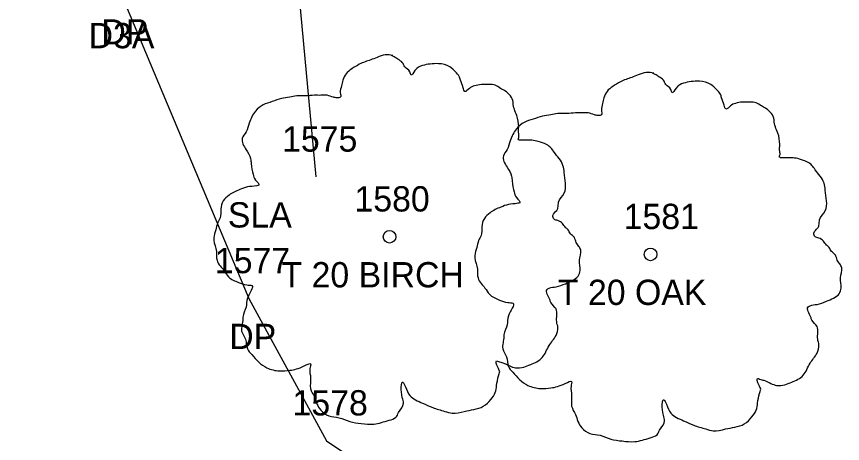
# Model space of a CAD drawing. Extents: x 1964982 to 1970452, y 1116335 to 1119906.
# Drawn here: x 1966585.21 to 1966617.84, y 1117418.71 to 1117435.59 of the extents above; entities that cross this region are included whole.
import ezdxf

# ---------------------------------------------------------------- set-up
doc = ezdxf.new("R2010")
doc.units = 0
for name, color, linetype in [('RD_EX_Driveway', 7, 'Continuous'), ('RD_EX_Driveway_txCode', 7, 'Continuous'), ('RD_EX_VEG', 7, 'Continuous'), ('RD_EX_VEG_txCode', 7, 'Continuous'), ('RD_SMD_Locator', 7, 'Continuous')]:
    doc.layers.add(name, color=color, linetype=linetype)

msp = doc.modelspace()

# ---------------------------------------------------------------- linework, layer by layer
at = {"layer": 'RD_EX_Driveway'}
msp.add_lwpolyline([(1966578.388, 1117408.593), (1966578.939, 1117419.648), (1966578.028, 1117435.239), (1966589.341, 1117436.481), (1966594.391, 1117424.44), (1966597.459, 1117418.815), (1966604.527, 1117414.058)], dxfattribs=at)
at = {"layer": 'RD_EX_VEG'}
msp.add_line((1966597.045, 1117429.245), (1966593.432, 1117467.989), dxfattribs=at)
for centre, radius in [((1966599.944, 1117426.878), 0.25), ((1966599.944, 1117426.878), 0.25), ((1966599.931, 1117426.86), 0.0001), ((1966599.931, 1117426.86), 0.0001), ((1966610.256, 1117426.183), 0.25), ((1966610.256, 1117426.183), 0.25), ((1966610.244, 1117426.164), 0.0001), ((1966610.244, 1117426.164), 0.0001)]:
    msp.add_circle(centre, radius, dxfattribs=at)
for points in [[(1966600.075, 1117434.046), (1966599.776, 1117434.071), (1966599.451, 1117433.971), (1966599.201, 1117433.871), (1966598.976, 1117433.796), (1966598.751, 1117433.696), (1966598.451, 1117433.521), (1966598.226, 1117433.321), (1966598.101, 1117433.071), (1966598.051, 1117432.846), (1966598.001, 1117432.571), (1966598.001, 1117432.396), (1966597.876, 1117432.371), (1966597.726, 1117432.396), (1966597.477, 1117432.471), (1966597.227, 1117432.471), (1966596.977, 1117432.471), (1966596.627, 1117432.446), (1966596.277, 1117432.446), (1966596.002, 1117432.396), (1966595.677, 1117432.346), (1966595.303, 1117432.221), (1966594.953, 1117432.096), (1966594.653, 1117431.847), (1966594.403, 1117431.372), (1966594.278, 1117431.022), (1966594.128, 1117430.772), (1966594.278, 1117430.322), (1966594.453, 1117429.972), (1966594.478, 1117429.772), (1966594.553, 1117429.348), (1966594.653, 1117429.123), (1966594.778, 1117428.923), (1966594.703, 1117428.898), (1966594.328, 1117428.848), (1966594.028, 1117428.748), (1966593.603, 1117428.523), (1966593.378, 1117428.298), (1966593.278, 1117427.973), (1966593.253, 1117427.623), (1966593.154, 1117427.424), (1966593.079, 1117427.149), (1966593.054, 1117427.074), (1966593.004, 1117426.749), (1966593.104, 1117426.299), (1966593.129, 1117425.949), (1966593.253, 1117425.724), (1966593.403, 1117425.549), (1966593.578, 1117425.299), (1966593.978, 1117425.075), (1966594.303, 1117424.975), (1966594.503, 1117424.95), (1966594.328, 1117424.45), (1966594.278, 1117424.1), (1966594.153, 1117423.7), (1966594.153, 1117423.625), (1966594.103, 1117423.15), (1966594.253, 1117422.825), (1966594.328, 1117422.451), (1966594.503, 1117422.226), (1966594.778, 1117421.926), (1966595.103, 1117421.701), (1966595.602, 1117421.576), (1966596.002, 1117421.601), (1966596.577, 1117421.776), (1966596.827, 1117421.851), (1966596.802, 1117421.676), (1966596.827, 1117421.301), (1966596.827, 1117420.876), (1966596.977, 1117420.552), (1966597.077, 1117420.277), (1966597.227, 1117420.027), (1966597.552, 1117419.802), (1966597.951, 1117419.727), (1966598.376, 1117419.577), (1966598.826, 1117419.502), (1966599.326, 1117419.477), (1966599.926, 1117419.627), (1966600.2, 1117419.752), (1966600.3, 1117419.927), (1966600.5, 1117420.302), (1966600.45, 1117420.527), (1966600.475, 1117421.126), (1966600.575, 1117420.951), (1966600.75, 1117420.601), (1966601.25, 1117420.302), (1966601.65, 1117420.127), (1966602.125, 1117419.977), (1966602.424, 1117419.902), (1966602.899, 1117419.977), (1966603.274, 1117420.052), (1966603.649, 1117420.177), (1966603.949, 1117420.452), (1966604.124, 1117420.726), (1966604.174, 1117421.001), (1966604.249, 1117421.376), (1966604.299, 1117421.551)], [(1966600.075, 1117434.046), (1966599.776, 1117434.071), (1966599.451, 1117433.971), (1966599.201, 1117433.871), (1966598.976, 1117433.796), (1966598.751, 1117433.696), (1966598.451, 1117433.521), (1966598.226, 1117433.321), (1966598.101, 1117433.071), (1966598.051, 1117432.846), (1966598.001, 1117432.571), (1966598.001, 1117432.396), (1966597.876, 1117432.371), (1966597.726, 1117432.396), (1966597.477, 1117432.471), (1966597.227, 1117432.471), (1966596.977, 1117432.471), (1966596.627, 1117432.446), (1966596.277, 1117432.446), (1966596.002, 1117432.396), (1966595.677, 1117432.346), (1966595.303, 1117432.221), (1966594.953, 1117432.096), (1966594.653, 1117431.847), (1966594.403, 1117431.372), (1966594.278, 1117431.022), (1966594.128, 1117430.772), (1966594.278, 1117430.322), (1966594.453, 1117429.972), (1966594.478, 1117429.772), (1966594.553, 1117429.348), (1966594.653, 1117429.123), (1966594.778, 1117428.923), (1966594.703, 1117428.898), (1966594.328, 1117428.848), (1966594.028, 1117428.748), (1966593.603, 1117428.523), (1966593.378, 1117428.298), (1966593.278, 1117427.973), (1966593.253, 1117427.623), (1966593.154, 1117427.424), (1966593.079, 1117427.149), (1966593.054, 1117427.074), (1966593.004, 1117426.749), (1966593.104, 1117426.299), (1966593.129, 1117425.949), (1966593.253, 1117425.724), (1966593.403, 1117425.549), (1966593.578, 1117425.299), (1966593.978, 1117425.075), (1966594.303, 1117424.975), (1966594.503, 1117424.95), (1966594.328, 1117424.45), (1966594.278, 1117424.1), (1966594.153, 1117423.7), (1966594.153, 1117423.625), (1966594.103, 1117423.15), (1966594.253, 1117422.825), (1966594.328, 1117422.451), (1966594.503, 1117422.226), (1966594.778, 1117421.926), (1966595.103, 1117421.701), (1966595.602, 1117421.576), (1966596.002, 1117421.601), (1966596.577, 1117421.776), (1966596.827, 1117421.851), (1966596.802, 1117421.676), (1966596.827, 1117421.301), (1966596.827, 1117420.876), (1966596.977, 1117420.552), (1966597.077, 1117420.277), (1966597.227, 1117420.027), (1966597.552, 1117419.802), (1966597.951, 1117419.727), (1966598.376, 1117419.577), (1966598.826, 1117419.502), (1966599.326, 1117419.477), (1966599.926, 1117419.627), (1966600.2, 1117419.752), (1966600.3, 1117419.927), (1966600.5, 1117420.302), (1966600.45, 1117420.527), (1966600.475, 1117421.126), (1966600.575, 1117420.951), (1966600.75, 1117420.601), (1966601.25, 1117420.302), (1966601.65, 1117420.127), (1966602.125, 1117419.977), (1966602.424, 1117419.902), (1966602.899, 1117419.977), (1966603.274, 1117420.052), (1966603.649, 1117420.177), (1966603.949, 1117420.452), (1966604.124, 1117420.726), (1966604.174, 1117421.001), (1966604.249, 1117421.376), (1966604.299, 1117421.551)], [(1966604.299, 1117421.551), (1966604.224, 1117421.726), (1966604.174, 1117421.976), (1966604.249, 1117421.951), (1966604.424, 1117421.901), (1966604.698, 1117421.776), (1966604.923, 1117421.701), (1966605.248, 1117421.726), (1966605.523, 1117421.826), (1966605.973, 1117422.101), (1966606.248, 1117422.576), (1966606.523, 1117422.975), (1966606.598, 1117423.3), (1966606.548, 1117423.525), (1966606.523, 1117424.025), (1966606.323, 1117424.275), (1966606.273, 1117424.4), (1966606.173, 1117424.8), (1966606.248, 1117424.85), (1966606.523, 1117424.9), (1966606.897, 1117425.025), (1966607.172, 1117425.149), (1966607.397, 1117425.324), (1966607.472, 1117425.549), (1966607.447, 1117425.949), (1966607.497, 1117426.349), (1966607.422, 1117426.499), (1966607.322, 1117426.649), (1966607.247, 1117426.849), (1966607.097, 1117426.999), (1966606.997, 1117427.149), (1966606.897, 1117427.249), (1966606.773, 1117427.399), (1966606.598, 1117427.523), (1966606.448, 1117427.573), (1966606.398, 1117427.723), (1966606.548, 1117427.923), (1966606.598, 1117428.023), (1966606.623, 1117428.248), (1966606.848, 1117428.598), (1966606.897, 1117428.998), (1966606.848, 1117429.423), (1966606.798, 1117429.698), (1966606.648, 1117429.972), (1966606.448, 1117430.222), (1966606.323, 1117430.397), (1966606.148, 1117430.522), (1966605.823, 1117430.647), (1966605.573, 1117430.697), (1966605.223, 1117430.697), (1966605.023, 1117430.747), (1966605.048, 1117430.797), (1966605.048, 1117430.947), (1966605.048, 1117431.222), (1966604.973, 1117431.672), (1966604.823, 1117432.171), (1966604.823, 1117432.196), (1966604.723, 1117432.446), (1966604.499, 1117432.646), (1966604.324, 1117432.746), (1966604.124, 1117432.871), (1966603.874, 1117432.896), (1966603.574, 1117432.896), (1966603.299, 1117432.846), (1966603.099, 1117432.746), (1966602.924, 1117432.621), (1966602.849, 1117432.771), (1966602.749, 1117433.071), (1966602.699, 1117433.221), (1966602.549, 1117433.396), (1966602.325, 1117433.596), (1966601.875, 1117433.721), (1966601.25, 1117433.646), (1966600.95, 1117433.446), (1966600.8, 1117433.271), (1966600.75, 1117433.396), (1966600.55, 1117433.596), (1966600.45, 1117433.771), (1966600.275, 1117433.896), (1966600.125, 1117433.996), (1966600.025, 1117434.046)], [(1966604.299, 1117421.551), (1966604.224, 1117421.726), (1966604.174, 1117421.976), (1966604.249, 1117421.951), (1966604.424, 1117421.901), (1966604.698, 1117421.776), (1966604.923, 1117421.701), (1966605.248, 1117421.726), (1966605.523, 1117421.826), (1966605.973, 1117422.101), (1966606.248, 1117422.576), (1966606.523, 1117422.975), (1966606.598, 1117423.3), (1966606.548, 1117423.525), (1966606.523, 1117424.025), (1966606.323, 1117424.275), (1966606.273, 1117424.4), (1966606.173, 1117424.8), (1966606.248, 1117424.85), (1966606.523, 1117424.9), (1966606.897, 1117425.025), (1966607.172, 1117425.149), (1966607.397, 1117425.324), (1966607.472, 1117425.549), (1966607.447, 1117425.949), (1966607.497, 1117426.349), (1966607.422, 1117426.499), (1966607.322, 1117426.649), (1966607.247, 1117426.849), (1966607.097, 1117426.999), (1966606.997, 1117427.149), (1966606.897, 1117427.249), (1966606.773, 1117427.399), (1966606.598, 1117427.523), (1966606.448, 1117427.573), (1966606.398, 1117427.723), (1966606.548, 1117427.923), (1966606.598, 1117428.023), (1966606.623, 1117428.248), (1966606.848, 1117428.598), (1966606.897, 1117428.998), (1966606.848, 1117429.423), (1966606.798, 1117429.698), (1966606.648, 1117429.972), (1966606.448, 1117430.222), (1966606.323, 1117430.397), (1966606.148, 1117430.522), (1966605.823, 1117430.647), (1966605.573, 1117430.697), (1966605.223, 1117430.697), (1966605.023, 1117430.747), (1966605.048, 1117430.797), (1966605.048, 1117430.947), (1966605.048, 1117431.222), (1966604.973, 1117431.672), (1966604.823, 1117432.171), (1966604.823, 1117432.196), (1966604.723, 1117432.446), (1966604.499, 1117432.646), (1966604.324, 1117432.746), (1966604.124, 1117432.871), (1966603.874, 1117432.896), (1966603.574, 1117432.896), (1966603.299, 1117432.846), (1966603.099, 1117432.746), (1966602.924, 1117432.621), (1966602.849, 1117432.771), (1966602.749, 1117433.071), (1966602.699, 1117433.221), (1966602.549, 1117433.396), (1966602.325, 1117433.596), (1966601.875, 1117433.721), (1966601.25, 1117433.646), (1966600.95, 1117433.446), (1966600.8, 1117433.271), (1966600.75, 1117433.396), (1966600.55, 1117433.596), (1966600.45, 1117433.771), (1966600.275, 1117433.896), (1966600.125, 1117433.996), (1966600.025, 1117434.046)], [(1966610.388, 1117433.35), (1966610.088, 1117433.375), (1966609.763, 1117433.275), (1966609.514, 1117433.175), (1966609.289, 1117433.1), (1966609.064, 1117433), (1966608.764, 1117432.825), (1966608.539, 1117432.625), (1966608.414, 1117432.375), (1966608.364, 1117432.151), (1966608.314, 1117431.876), (1966608.314, 1117431.701), (1966608.189, 1117431.676), (1966608.039, 1117431.701), (1966607.789, 1117431.776), (1966607.539, 1117431.776), (1966607.289, 1117431.776), (1966606.94, 1117431.751), (1966606.59, 1117431.751), (1966606.315, 1117431.701), (1966605.99, 1117431.651), (1966605.615, 1117431.526), (1966605.265, 1117431.401), (1966604.966, 1117431.151), (1966604.716, 1117430.676), (1966604.591, 1117430.326), (1966604.441, 1117430.076), (1966604.591, 1117429.627), (1966604.766, 1117429.277), (1966604.791, 1117429.077), (1966604.866, 1117428.652), (1966604.966, 1117428.427), (1966605.09, 1117428.227), (1966605.016, 1117428.202), (1966604.641, 1117428.152), (1966604.341, 1117428.052), (1966603.916, 1117427.827), (1966603.691, 1117427.603), (1966603.591, 1117427.278), (1966603.566, 1117426.928), (1966603.466, 1117426.728), (1966603.391, 1117426.453), (1966603.366, 1117426.378), (1966603.316, 1117426.053), (1966603.416, 1117425.603), (1966603.441, 1117425.254), (1966603.566, 1117425.029), (1966603.716, 1117424.854), (1966603.891, 1117424.604), (1966604.291, 1117424.379), (1966604.616, 1117424.279), (1966604.816, 1117424.254), (1966604.641, 1117423.754), (1966604.591, 1117423.404), (1966604.466, 1117423.005), (1966604.466, 1117422.93), (1966604.416, 1117422.455), (1966604.566, 1117422.13), (1966604.641, 1117421.755), (1966604.816, 1117421.53), (1966605.09, 1117421.23), (1966605.415, 1117421.005), (1966605.915, 1117420.88), (1966606.315, 1117420.905), (1966606.89, 1117421.08), (1966607.14, 1117421.155), (1966607.115, 1117420.98), (1966607.14, 1117420.606), (1966607.14, 1117420.181), (1966607.289, 1117419.856), (1966607.389, 1117419.581), (1966607.539, 1117419.331), (1966607.864, 1117419.106), (1966608.264, 1117419.031), (1966608.689, 1117418.881), (1966609.139, 1117418.806), (1966609.638, 1117418.781), (1966610.238, 1117418.931), (1966610.513, 1117419.056), (1966610.613, 1117419.231), (1966610.813, 1117419.606), (1966610.763, 1117419.831), (1966610.788, 1117420.431), (1966610.888, 1117420.256), (1966611.063, 1117419.906), (1966611.563, 1117419.606), (1966611.962, 1117419.431), (1966612.437, 1117419.281), (1966612.737, 1117419.206), (1966613.212, 1117419.281), (1966613.587, 1117419.356), (1966613.962, 1117419.481), (1966614.261, 1117419.756), (1966614.436, 1117420.031), (1966614.486, 1117420.306), (1966614.561, 1117420.681), (1966614.611, 1117420.855)], [(1966610.388, 1117433.35), (1966610.088, 1117433.375), (1966609.763, 1117433.275), (1966609.514, 1117433.175), (1966609.289, 1117433.1), (1966609.064, 1117433), (1966608.764, 1117432.825), (1966608.539, 1117432.625), (1966608.414, 1117432.375), (1966608.364, 1117432.151), (1966608.314, 1117431.876), (1966608.314, 1117431.701), (1966608.189, 1117431.676), (1966608.039, 1117431.701), (1966607.789, 1117431.776), (1966607.539, 1117431.776), (1966607.289, 1117431.776), (1966606.94, 1117431.751), (1966606.59, 1117431.751), (1966606.315, 1117431.701), (1966605.99, 1117431.651), (1966605.615, 1117431.526), (1966605.265, 1117431.401), (1966604.966, 1117431.151), (1966604.716, 1117430.676), (1966604.591, 1117430.326), (1966604.441, 1117430.076), (1966604.591, 1117429.627), (1966604.766, 1117429.277), (1966604.791, 1117429.077), (1966604.866, 1117428.652), (1966604.966, 1117428.427), (1966605.09, 1117428.227), (1966605.016, 1117428.202), (1966604.641, 1117428.152), (1966604.341, 1117428.052), (1966603.916, 1117427.827), (1966603.691, 1117427.603), (1966603.591, 1117427.278), (1966603.566, 1117426.928), (1966603.466, 1117426.728), (1966603.391, 1117426.453), (1966603.366, 1117426.378), (1966603.316, 1117426.053), (1966603.416, 1117425.603), (1966603.441, 1117425.254), (1966603.566, 1117425.029), (1966603.716, 1117424.854), (1966603.891, 1117424.604), (1966604.291, 1117424.379), (1966604.616, 1117424.279), (1966604.816, 1117424.254), (1966604.641, 1117423.754), (1966604.591, 1117423.404), (1966604.466, 1117423.005), (1966604.466, 1117422.93), (1966604.416, 1117422.455), (1966604.566, 1117422.13), (1966604.641, 1117421.755), (1966604.816, 1117421.53), (1966605.09, 1117421.23), (1966605.415, 1117421.005), (1966605.915, 1117420.88), (1966606.315, 1117420.905), (1966606.89, 1117421.08), (1966607.14, 1117421.155), (1966607.115, 1117420.98), (1966607.14, 1117420.606), (1966607.14, 1117420.181), (1966607.289, 1117419.856), (1966607.389, 1117419.581), (1966607.539, 1117419.331), (1966607.864, 1117419.106), (1966608.264, 1117419.031), (1966608.689, 1117418.881), (1966609.139, 1117418.806), (1966609.638, 1117418.781), (1966610.238, 1117418.931), (1966610.513, 1117419.056), (1966610.613, 1117419.231), (1966610.813, 1117419.606), (1966610.763, 1117419.831), (1966610.788, 1117420.431), (1966610.888, 1117420.256), (1966611.063, 1117419.906), (1966611.563, 1117419.606), (1966611.962, 1117419.431), (1966612.437, 1117419.281), (1966612.737, 1117419.206), (1966613.212, 1117419.281), (1966613.587, 1117419.356), (1966613.962, 1117419.481), (1966614.261, 1117419.756), (1966614.436, 1117420.031), (1966614.486, 1117420.306), (1966614.561, 1117420.681), (1966614.611, 1117420.855)], [(1966614.611, 1117420.855), (1966614.536, 1117421.03), (1966614.486, 1117421.28), (1966614.561, 1117421.255), (1966614.736, 1117421.205), (1966615.011, 1117421.08), (1966615.236, 1117421.005), (1966615.561, 1117421.03), (1966615.836, 1117421.13), (1966616.286, 1117421.405), (1966616.56, 1117421.88), (1966616.835, 1117422.28), (1966616.91, 1117422.605), (1966616.86, 1117422.83), (1966616.835, 1117423.329), (1966616.635, 1117423.579), (1966616.585, 1117423.704), (1966616.485, 1117424.104), (1966616.56, 1117424.154), (1966616.835, 1117424.204), (1966617.21, 1117424.329), (1966617.485, 1117424.454), (1966617.71, 1117424.629), (1966617.785, 1117424.854), (1966617.76, 1117425.254), (1966617.81, 1117425.653), (1966617.735, 1117425.803), (1966617.635, 1117425.953), (1966617.56, 1117426.153), (1966617.41, 1117426.303), (1966617.31, 1117426.453), (1966617.21, 1117426.553), (1966617.085, 1117426.703), (1966616.91, 1117426.828), (1966616.76, 1117426.878), (1966616.71, 1117427.028), (1966616.86, 1117427.228), (1966616.91, 1117427.328), (1966616.935, 1117427.553), (1966617.16, 1117427.902), (1966617.21, 1117428.302), (1966617.16, 1117428.727), (1966617.11, 1117429.002), (1966616.96, 1117429.277), (1966616.76, 1117429.527), (1966616.635, 1117429.702), (1966616.46, 1117429.827), (1966616.136, 1117429.952), (1966615.886, 1117430.001), (1966615.536, 1117430.001), (1966615.336, 1117430.051), (1966615.361, 1117430.101), (1966615.361, 1117430.251), (1966615.361, 1117430.526), (1966615.286, 1117430.976), (1966615.136, 1117431.476), (1966615.136, 1117431.501), (1966615.036, 1117431.751), (1966614.811, 1117431.951), (1966614.636, 1117432.051), (1966614.436, 1117432.176), (1966614.186, 1117432.201), (1966613.887, 1117432.201), (1966613.612, 1117432.151), (1966613.412, 1117432.051), (1966613.237, 1117431.926), (1966613.162, 1117432.076), (1966613.062, 1117432.375), (1966613.012, 1117432.525), (1966612.862, 1117432.7), (1966612.637, 1117432.9), (1966612.187, 1117433.025), (1966611.563, 1117432.95), (1966611.263, 1117432.75), (1966611.113, 1117432.575), (1966611.063, 1117432.7), (1966610.863, 1117432.9), (1966610.763, 1117433.075), (1966610.588, 1117433.2), (1966610.438, 1117433.3), (1966610.338, 1117433.35)], [(1966614.611, 1117420.855), (1966614.536, 1117421.03), (1966614.486, 1117421.28), (1966614.561, 1117421.255), (1966614.736, 1117421.205), (1966615.011, 1117421.08), (1966615.236, 1117421.005), (1966615.561, 1117421.03), (1966615.836, 1117421.13), (1966616.286, 1117421.405), (1966616.56, 1117421.88), (1966616.835, 1117422.28), (1966616.91, 1117422.605), (1966616.86, 1117422.83), (1966616.835, 1117423.329), (1966616.635, 1117423.579), (1966616.585, 1117423.704), (1966616.485, 1117424.104), (1966616.56, 1117424.154), (1966616.835, 1117424.204), (1966617.21, 1117424.329), (1966617.485, 1117424.454), (1966617.71, 1117424.629), (1966617.785, 1117424.854), (1966617.76, 1117425.254), (1966617.81, 1117425.653), (1966617.735, 1117425.803), (1966617.635, 1117425.953), (1966617.56, 1117426.153), (1966617.41, 1117426.303), (1966617.31, 1117426.453), (1966617.21, 1117426.553), (1966617.085, 1117426.703), (1966616.91, 1117426.828), (1966616.76, 1117426.878), (1966616.71, 1117427.028), (1966616.86, 1117427.228), (1966616.91, 1117427.328), (1966616.935, 1117427.553), (1966617.16, 1117427.902), (1966617.21, 1117428.302), (1966617.16, 1117428.727), (1966617.11, 1117429.002), (1966616.96, 1117429.277), (1966616.76, 1117429.527), (1966616.635, 1117429.702), (1966616.46, 1117429.827), (1966616.136, 1117429.952), (1966615.886, 1117430.001), (1966615.536, 1117430.001), (1966615.336, 1117430.051), (1966615.361, 1117430.101), (1966615.361, 1117430.251), (1966615.361, 1117430.526), (1966615.286, 1117430.976), (1966615.136, 1117431.476), (1966615.136, 1117431.501), (1966615.036, 1117431.751), (1966614.811, 1117431.951), (1966614.636, 1117432.051), (1966614.436, 1117432.176), (1966614.186, 1117432.201), (1966613.887, 1117432.201), (1966613.612, 1117432.151), (1966613.412, 1117432.051), (1966613.237, 1117431.926), (1966613.162, 1117432.076), (1966613.062, 1117432.375), (1966613.012, 1117432.525), (1966612.862, 1117432.7), (1966612.637, 1117432.9), (1966612.187, 1117433.025), (1966611.563, 1117432.95), (1966611.263, 1117432.75), (1966611.113, 1117432.575), (1966611.063, 1117432.7), (1966610.863, 1117432.9), (1966610.763, 1117433.075), (1966610.588, 1117433.2), (1966610.438, 1117433.3), (1966610.338, 1117433.35)]]:
    msp.add_spline(points, degree=3, dxfattribs=at)
at = {"layer": 'RD_SMD_Locator'}
for centre in [(1966597.045, 1117429.245), (1966597.045, 1117429.245), (1966594.391, 1117424.44), (1966594.391, 1117424.44), (1966597.459, 1117418.815), (1966597.459, 1117418.815)]:
    msp.add_circle(centre, 0.001, dxfattribs=at)

# ---------------------------------------------------------------- texts
at = {"layer": 'RD_EX_Driveway_txCode'}
for s, p in [('DP', (1966588.561, 1117434.481)), ('DP', (1966588.561, 1117434.481)), ('D3A', (1966588.056, 1117434.331)), ('D3A', (1966588.056, 1117434.331)), ('1577', (1966593.045, 1117425.44)), ('1577', (1966593.045, 1117425.44)), ('DP', (1966593.612, 1117422.44)), ('DP', (1966593.612, 1117422.44)), ('1578', (1966596.112, 1117419.815)), ('1578', (1966596.112, 1117419.815))]:
    msp.add_text(s, height=1, dxfattribs=at).set_placement(p)
at = {"layer": 'RD_EX_VEG_txCode'}
for s, p in [('1575', (1966595.699, 1117430.245)), ('1575', (1966595.699, 1117430.245)), ('1580', (1966598.558, 1117427.878)), ('1580', (1966598.558, 1117427.878)), ('SLA', (1966593.557, 1117427.245)), ('SLA', (1966593.557, 1117427.245)), ('1581', (1966609.193, 1117427.183)), ('1581', (1966609.193, 1117427.183)), ('T 20 BIRCH', (1966595.676, 1117424.878)), ('T 20 BIRCH', (1966595.676, 1117424.878)), ('T 20 OAK', (1966606.595, 1117424.183)), ('T 20 OAK', (1966606.595, 1117424.183))]:
    msp.add_text(s, height=1, dxfattribs=at).set_placement(p)

doc.saveas('drawing.dxf')
